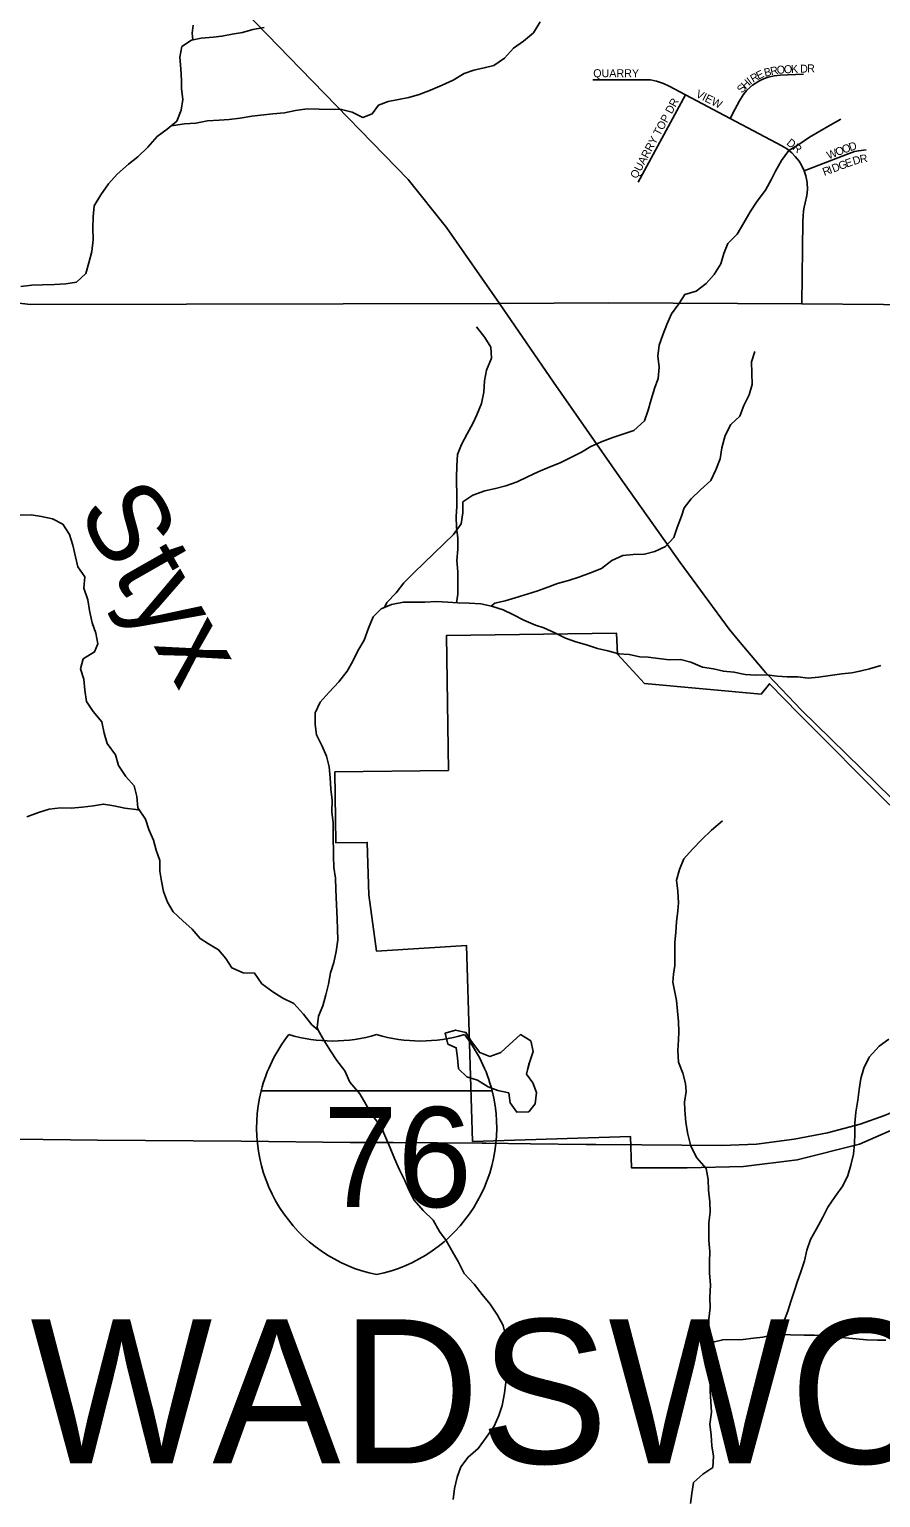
# Model space of a CAD drawing. Extents: x 1985906 to 2277390, y 930619 to 1324581.
# Drawn here: x 2165801 to 2171119, y 1102890 to 1112061 of the extents above; entities that cross this region are included whole.
import ezdxf

# ---------------------------------------------------------------- set-up
doc = ezdxf.new("R2010")
doc.units = 0
for name, color, linetype in [('GM_X_Corporation', 7, 'Continuous'), ('GM_X_Interstate_Location', 7, 'Continuous'), ('GM_X_Interstate_Route', 7, 'Continuous'), ('GM_X_Interstate_Shield', 7, 'Continuous'), ('GM_X_Minor_Lake', 7, 'Continuous'), ('GM_X_Minor_River', 7, 'Continuous'), ('GM_X_Minor_River_Text', 7, 'Continuous'), ('GM_X_State_Route', 7, 'Continuous'), ('GM_X_Township_Road', 7, 'Continuous'), ('GM_X_Township_Subdivision', 7, 'Continuous'), ('GM_X_Township_Subdivision_Text', 7, 'Continuous'), ('GM_X_Township_Text', 7, 'Continuous')]:
    doc.layers.add(name, color=color, linetype=linetype)

msp = doc.modelspace()

# ---------------------------------------------------------------- linework, layer by layer
at = {"layer": 'GM_X_Corporation'}
msp.add_lwpolyline([(2171300.4, 1105236.1), (2170987.2, 1105097.6), (2170598.2, 1104999.5), (2170261.5, 1104957.3), (2169911.1, 1104949.2), (2169562.4, 1104950.4), (2169556.4, 1105145.4), (2168569.5, 1105114.6), (2168531.3, 1106339.4), (2167970.3, 1106302.3), (2167922.1, 1106655.2), (2167911.9, 1106982.2), (2167715.8, 1106979.5), (2167709.7, 1107422.7), (2168419, 1107432.4), (2168407.4, 1108275.7), (2169468.6, 1108290.2), (2169474.8, 1108158.3), (2169643, 1107975.9), (2170372.1, 1107907.9), (2170423.6, 1107973.1), (2170608.8, 1107785.7), (2171176.3, 1107215.7)], dxfattribs=at)
at = {"layer": 'GM_X_Interstate_Route'}
for points in [[(2169340.5, 1105095.5), (2169627.6, 1105092.7), (2170126.8, 1105089.2), (2170343.8, 1105098.7), (2170579, 1105129.1), (2170786.5, 1105168.2), (2170990.8, 1105223.5), (2171143.3, 1105277.6), (2171307.3, 1105346.1), (2171741.4, 1105556.1)], [(2161235, 1105171.6), (2161289.1, 1105171.1), (2161323.8, 1105170.8), (2161961, 1105162.1), (2161969.6, 1105161.9), (2162147.6, 1105159.5), (2162924.5, 1105156), (2163727.5, 1105147.4), (2164561.7, 1105143), (2165425.4, 1105133.5), (2165719.2, 1105129.6), (2166226.6, 1105123.1), (2167123.3, 1105116.1), (2167804.7, 1105109.2), (2168074.7, 1105108.3), (2168630.3, 1105104), (2168655.3, 1105103.6)], [(2168655.3, 1105103.6), (2168931.5, 1105099.6), (2169279.6, 1105096.1), (2169340.5, 1105095.5)]]:
    msp.add_lwpolyline(points, dxfattribs=at)
at = {"layer": 'GM_X_Interstate_Shield'}
for p, q in [((2167249.1, 1105431.2), (2168691.8, 1105431.2)), ((2168691.8, 1105431.2), (2167249.1, 1105431.2)), ((2168691.8, 1105431.2), (2167249.1, 1105431.2))]:
    msp.add_line(p, q, dxfattribs=at)
for centre, start, end in [((2168158, 1105201.3), 141.66896, 165.80665), ((2167696.5, 1106679.4), 253.00908, 286.99093), ((2168244.4, 1106679.4), 253.00908, 286.99093), ((2167783, 1105201.3), 14.19335, 38.33104), ((2168158, 1105201.3), 165.80665, 258.46304), ((2167783, 1105201.3), 281.53696, 14.19335)]:
    msp.add_arc(centre, 937.5, start, end, dxfattribs=at)
at = {"layer": 'GM_X_Minor_Lake'}
for points in [[(2168914, 1105568), (2168924.5, 1105608.5), (2168949.2, 1105677.1), (2168934, 1105742.9), (2168869.2, 1105781.8), (2168798.2, 1105718.3), (2168747, 1105671.3), (2168677.4, 1105645.9), (2168614.9, 1105670.8), (2168563.5, 1105740), (2168528.4, 1105795.4), (2168464.1, 1105810.3), (2168398.3, 1105791), (2168415.6, 1105723.2)], [(2168921.4, 1105596.7), (2168924.5, 1105608.5), (2168949.2, 1105677.1), (2168934, 1105742.9), (2168869.2, 1105781.8), (2168798.2, 1105718.3), (2168747, 1105671.3), (2168677.4, 1105645.9), (2168614.9, 1105670.8), (2168563.5, 1105740), (2168528.4, 1105795.4), (2168464.1, 1105810.3), (2168398.3, 1105791), (2168415.6, 1105723.2)], [(2168415.6, 1105723.2), (2168468.1, 1105700.1), (2168475.3, 1105636.2), (2168482.6, 1105568.2), (2168533.6, 1105519), (2168600.1, 1105498.2), (2168667, 1105455.4), (2168727.5, 1105432.5), (2168795.8, 1105417.8), (2168805, 1105355.8), (2168846.1, 1105298.5), (2168920.2, 1105299.9), (2168961.3, 1105350.7), (2168970, 1105421), (2168946.9, 1105480.7), (2168905.8, 1105536), (2168914, 1105568)], [(2168415.6, 1105723.2), (2168468.1, 1105700.1), (2168475.3, 1105636.2), (2168482.6, 1105568.2), (2168533.6, 1105519), (2168600.1, 1105498.2), (2168667, 1105455.4), (2168727.5, 1105432.5), (2168795.8, 1105417.8), (2168805, 1105355.8), (2168846.1, 1105298.5), (2168920.2, 1105299.9), (2168961.3, 1105350.7), (2168970, 1105421), (2168946.9, 1105480.7), (2168905.8, 1105536), (2168921.4, 1105596.7)]]:
    msp.add_lwpolyline(points, dxfattribs=at)
at = {"layer": 'GM_X_Minor_River'}
for points in [[(2165747.8, 1110455.7), (2165815.7, 1110463), (2165883.8, 1110464.2), (2165957.9, 1110467.6), (2166027.9, 1110470.9), (2166095.8, 1110482.2), (2166152.9, 1110535.4), (2166173.6, 1110601.9), (2166192.3, 1110674.3), (2166199, 1110746.6), (2166197.6, 1110818.7), (2166200.3, 1110890.8), (2166205, 1110959.1), (2166247.8, 1111028), (2166294.6, 1111097), (2166349.5, 1111156.1), (2166420.5, 1111219.5), (2166479.7, 1111264.7), (2166540.6, 1111325.9), (2166599.5, 1111391.1), (2166662.7, 1111436.4), (2166721.9, 1111487.6), (2166748.6, 1111556.2), (2166759.4, 1111622.5), (2166752.1, 1111690.5), (2166751.2, 1111740.5), (2166747.8, 1111814.6), (2166740.4, 1111886.6), (2166753.2, 1111952.9), (2166814.5, 1111994.1), (2166874.4, 1112005.3), (2166948.4, 1112012.7), (2167004.4, 1112017.7), (2167068.2, 1112030.9), (2167132.1, 1112042.1), (2167197.8, 1112059.4), (2167267.7, 1112072.7)], [(2166688.1, 1111458.4), (2166702.3, 1111461.2), (2166770.3, 1111470.4), (2166840.3, 1111475.8), (2166914.1, 1111489.2), (2166986.1, 1111494.5), (2167050.1, 1111497.7), (2167118.1, 1111507), (2167189.9, 1111518.4), (2167321.9, 1111532.8), (2167395.8, 1111540.2), (2167463.7, 1111553.5), (2167537.5, 1111564.9), (2167611.7, 1111562.3), (2167751.9, 1111560.9), (2167818.3, 1111544.1), (2167885, 1111511.3), (2167942.7, 1111532.4), (2167981.7, 1111587.2), (2168043.4, 1111610.4), (2168107.2, 1111623.6), (2168171.1, 1111634.8), (2168236.8, 1111654.1), (2168306.4, 1111681.4), (2168379.9, 1111712.9), (2168449.4, 1111744.2), (2168516.8, 1111785.5), (2168578.5, 1111806.7), (2168642.3, 1111819.9), (2168702.1, 1111835.1), (2168769.3, 1111880.4), (2168826.2, 1111943.6), (2168887.5, 1111986.8), (2168950.6, 1112040.1), (2168991.4, 1112106.9)], [(2166822.9, 1111995.7), (2166817.7, 1112036.3), (2166824.8, 1112086.5)], [(2168018.9, 1108450.1), (2168033.8, 1108480.9), (2168092.7, 1108542.1), (2168139.6, 1108603.1), (2168204.5, 1108668.4), (2168265.5, 1108725.7), (2168328.5, 1108787), (2168391.4, 1108850.2), (2168450.4, 1108905.4), (2168499.2, 1108972.5), (2168508, 1109040.7), (2168508.7, 1109108.9), (2168572, 1109152.1), (2168645.6, 1109177.5), (2168713.4, 1109192.8), (2168777.2, 1109210.1), (2168848.8, 1109235.4), (2168912.3, 1109266.7), (2168979.8, 1109298), (2169047.4, 1109327.3), (2169117, 1109352.6), (2169184.4, 1109385.9), (2169249.9, 1109419.2), (2169309.3, 1109454.4), (2169378.9, 1109485.7), (2169446.5, 1109511), (2169514.1, 1109534.3), (2169577.8, 1109555.6), (2169642.8, 1109614.9), (2169667.6, 1109681.4), (2169686.4, 1109747.9), (2169707.1, 1109818.4), (2169730, 1109881), (2169734.7, 1109951.2), (2169727.4, 1110019.1), (2169736.1, 1110087.4), (2169759, 1110152), (2169783.8, 1110216.5), (2169812.6, 1110283.2), (2169857.5, 1110346.1), (2169896.4, 1110405), (2169966.1, 1110426.3), (2170029.3, 1110473.6), (2170078.3, 1110530.6), (2170121.2, 1110595.5), (2170140, 1110659.9), (2170164.9, 1110722.5), (2170221.8, 1110781.6), (2170264.6, 1110852.6), (2170303.3, 1110921.4), (2170348.2, 1110988.4), (2170398.9, 1111057.4), (2170437.7, 1111124.2), (2170462.8, 1111174.8), (2170499.6, 1111241.6), (2170544.5, 1111304.5), (2170607.9, 1111341.8), (2170675.2, 1111387.1), (2170738.6, 1111424.3), (2170803.9, 1111461.6), (2170869.3, 1111498.9)], [(2168469.5, 1108479.9), (2168477.4, 1108533.3), (2168478.1, 1108603.4), (2168476.8, 1108673.5), (2168471.5, 1108743.5), (2168478.1, 1108813.8), (2168476.8, 1108883.9), (2168469.6, 1108949.9), (2168468.3, 1109018), (2168471.2, 1109080.1), (2168472.2, 1109130.2), (2168469.8, 1109262.4), (2168472.4, 1109334.6), (2168475.1, 1109404.8), (2168500, 1109467.3), (2168536.8, 1109534.1), (2168573.6, 1109602.9), (2168596.7, 1109653.4), (2168625.4, 1109724.1), (2168640.1, 1109794.5), (2168644.8, 1109864.7), (2168657.5, 1109933.1), (2168688.2, 1110007.8), (2168682.9, 1110075.8), (2168645.7, 1110137.2), (2168594.4, 1110202.3)], [(2168687.9, 1108459.3), (2168708.7, 1108477.5), (2168772.6, 1108490.7), (2168836.3, 1108509.9), (2168971.7, 1108552.5), (2169039.3, 1108577.8), (2169101, 1108599), (2169168.7, 1108618.3), (2169234.4, 1108639.6), (2169306, 1108667), (2169375.6, 1108694.3), (2169438.8, 1108743.6), (2169508.3, 1108774.9), (2169572.3, 1108780.1), (2169644.3, 1108783.5), (2169708.1, 1108798.7), (2169775.6, 1108830), (2169826.6, 1108887.1), (2169847.5, 1108949.5), (2169874.2, 1109020.2), (2169891.3, 1109072.6), (2169934.3, 1109127.5), (2169993.3, 1109184.7), (2170058.3, 1109242), (2170089.1, 1109308.7), (2170115.8, 1109379.3), (2170126.6, 1109447.6), (2170147.2, 1109524.1), (2170184, 1109592.9), (2170239.1, 1109644), (2170263.9, 1109710.6), (2170296.7, 1109777.3), (2170315.5, 1109841.8), (2170312.8, 1109984), (2170333.7, 1110048.5)], [(2167604.9, 1105810.3), (2167566.2, 1105843.6), (2167512.9, 1105910.7), (2167453.6, 1105975.7), (2167384.9, 1106010.5), (2167322.1, 1106049.4), (2167253, 1106100.2), (2167207.8, 1106165.5), (2167137.6, 1106168.2), (2167066.9, 1106198.9), (2167027.8, 1106258.3), (2166982.7, 1106311.6), (2166920, 1106348.4), (2166867.3, 1106381.5), (2166818.1, 1106440.7), (2166759.1, 1106491.7), (2166699.9, 1106548.7), (2166664.7, 1106610.1), (2166639.5, 1106675.8), (2166626.3, 1106739.7), (2166617.1, 1106803.6), (2166615.8, 1106869.7), (2166592.6, 1106933.4), (2166577.4, 1106997.2), (2166548.2, 1107062.8), (2166526.9, 1107128.5), (2166479.5, 1107197.7), (2166472.2, 1107269.7), (2166454.9, 1107335.5), (2166403.8, 1107394.6), (2166358.5, 1107461.9), (2166339.2, 1107529.7), (2166287.8, 1107600.9), (2166268.6, 1107664.6), (2166253.2, 1107736.4), (2166199.9, 1107799.6), (2166158.7, 1107862.9), (2166147.4, 1107932.8), (2166142.1, 1108002.8), (2166120.9, 1108066.6), (2166137.7, 1108129), (2166209, 1108172.4), (2166228.1, 1108222.8), (2166216.9, 1108288.7), (2166193.6, 1108354.4), (2166176.2, 1108430.2), (2166166.9, 1108498.2), (2166141.5, 1108569.8), (2166148.2, 1108642.1), (2166103, 1108703.3), (2166089.8, 1108765.2), (2166072.4, 1108839), (2166051.1, 1108904.7), (2166009.9, 1108970.1), (2165945.2, 1109002.9), (2165876.8, 1109017.6), (2165812.5, 1109028.5), (2165744.4, 1109027.2)], [(2167604.9, 1105810.3), (2167598.6, 1105826.2), (2167607.3, 1105896.4), (2167634.2, 1105961.1), (2167652.9, 1106029.5), (2167669.6, 1106098), (2167682.4, 1106168.3), (2167703.2, 1106232.8), (2167717.9, 1106301.2), (2167728.6, 1106373.6), (2167725.4, 1106437.6), (2167724.1, 1106505.7), (2167717.7, 1106637.8), (2167714.7, 1106689.8), (2167713.4, 1106760), (2167704.1, 1106825.9), (2167700.8, 1106896), (2167698.2, 1107036.2), (2167698.9, 1107104.3), (2167691.6, 1107174.3), (2167692.3, 1107246.4), (2167685, 1107314.4), (2167679.7, 1107386.4), (2167674.4, 1107454.4), (2167657.1, 1107520.2), (2167629.9, 1107583.8), (2167594.5, 1107655.3), (2167587.3, 1107719.3), (2167586, 1107791.4), (2167616.8, 1107858.1), (2167673.7, 1107921.2), (2167734.6, 1107984.5), (2167787.4, 1108051.6), (2167822.3, 1108114.3), (2167853.1, 1108179), (2167891.9, 1108245.9), (2167918.6, 1108320.5), (2167949.3, 1108391.2), (2167998.4, 1108442.2), (2168064, 1108467.5), (2168137.9, 1108482.9), (2168201.9, 1108484.1), (2168272, 1108483.4), (2168344.1, 1108486.7), (2168416.2, 1108484.1), (2168478.4, 1108479.2), (2168548.5, 1108476.5), (2168620.7, 1108471.9), (2168689, 1108459.1), (2168761.6, 1108434.4), (2168826.3, 1108403.6), (2168891, 1108370.7), (2168963.6, 1108340), (2169014, 1108322.9), (2169082.7, 1108292.1), (2169149.4, 1108257.3), (2169214, 1108234.5), (2169280.4, 1108215.7), (2169350.9, 1108193), (2169415.3, 1108178.1), (2169483.7, 1108159.4), (2169547.9, 1108156.6), (2169614.2, 1108141.8), (2169666.4, 1108138.8), (2169730.6, 1108131.9), (2169796.8, 1108123.2), (2169868.9, 1108124.5), (2169933.3, 1108107.7), (2170006, 1108077), (2170074.3, 1108066.2), (2170136.6, 1108051.4), (2170202.8, 1108046.6), (2170273.2, 1108031.9), (2170339.3, 1108027.1), (2170407.4, 1108028.4), (2170471.6, 1108021.6), (2170535.8, 1108016.7), (2170601.9, 1108016), (2170666.1, 1108009.2), (2170730.1, 1108014.3), (2170804, 1108025.8), (2170875.9, 1108035.1), (2170937.9, 1108042.3), (2170989.8, 1108051.2), (2171049.6, 1108066.4), (2171119.3, 1108087.7)], [(2166489.6, 1107183.1), (2166465.7, 1107187.4), (2166397.5, 1107196.2), (2166329.1, 1107210.9), (2166264.8, 1107221.8), (2166200.9, 1107210.6), (2166131, 1107203.2), (2166063, 1107196), (2165994.9, 1107198.7), (2165924.9, 1107189.4), (2165857.2, 1107170.1), (2165785.6, 1107142.7)], [(2170049.2, 1104363.2), (2170052, 1104427.4), (2170044.7, 1104495.4), (2170045.8, 1104545.5), (2170046.6, 1104605.6), (2170053.4, 1104673.8), (2170052.2, 1104737.9), (2170042.8, 1104809.9), (2170041.6, 1104878), (2170028.3, 1104945.9), (2169971, 1105012.9), (2169933.5, 1105086.3), (2169914.1, 1105160.1), (2169902.8, 1105234), (2169895.3, 1105310), (2169894.4, 1105360.1), (2169903.2, 1105426.4), (2169900.2, 1105476.4), (2169883, 1105542.2), (2169855.7, 1105609.8), (2169852.3, 1105681.9), (2169857.1, 1105750.1), (2169858.1, 1105800.2), (2169857, 1105864.3), (2169849.8, 1105928.3), (2169844.5, 1105994.3), (2169833.5, 1106046.2), (2169820.3, 1106110.1), (2169825.4, 1106160.2), (2169832.4, 1106214.5), (2169833.2, 1106278.6), (2169833.8, 1106356.8), (2169838.6, 1106420.9), (2169843.3, 1106487.2), (2169852.1, 1106555.4), (2169855.2, 1106605.6), (2169851.8, 1106677.6), (2169844.5, 1106747.6), (2169863.3, 1106814.1), (2169890.1, 1106880.7), (2169943.1, 1106939.8), (2170002, 1107001), (2170063, 1107058.2), (2170130, 1107117.6)], [(2168448.6, 1102878.8), (2168457.4, 1102947.1), (2168474.1, 1103017.5), (2168496.9, 1103082), (2168541.8, 1103143), (2168604.9, 1103196.2), (2168653.7, 1103265.3), (2168704.5, 1103336.3), (2168733.3, 1103403), (2168754.1, 1103465.5), (2168768.7, 1103541.9), (2168777.4, 1103612.2), (2168782.1, 1103684.4), (2168780.7, 1103760.5), (2168773.5, 1103824.5), (2168776, 1103904.7), (2168760.8, 1103964.5), (2168725.6, 1104030), (2168680.2, 1104099.2), (2168629.1, 1104158.4), (2168579.8, 1104223.6), (2168516.4, 1104290.6), (2168479, 1104364), (2168441.8, 1104429.4), (2168404.5, 1104496.8), (2168363.4, 1104552.2), (2168324, 1104623.6), (2168260.8, 1104682.5), (2168205.5, 1104747.6), (2168174.3, 1104809.1), (2168147.1, 1104870.7), (2168113.8, 1104938.2), (2168082.5, 1105007.7), (2168055.2, 1105075.3), (2168028, 1105136.9), (2167998.7, 1105206.5), (2167943.3, 1105279.6), (2167904, 1105347), (2167864.7, 1105412.4), (2167803.2, 1105485.4), (2167771.9, 1105554.9), (2167722.6, 1105620.1), (2167681.4, 1105681.5), (2167640.1, 1105746.8), (2167604.9, 1105810.3)], [(2170496.9, 1103908.5), (2170496.6, 1103916.6), (2170512.9, 1103983.2), (2170539.6, 1104053.8), (2170558.5, 1104114.3), (2170581.2, 1104182.8), (2170598.3, 1104235.2), (2170621.1, 1104299.8), (2170643.9, 1104368.3), (2170658.6, 1104436.7), (2170681.4, 1104503.2), (2170718.3, 1104568), (2170755, 1104636.8), (2170789.8, 1104703.6), (2170834.6, 1104770.6), (2170883.5, 1104837.6), (2170914.3, 1104902.3), (2170933.1, 1104966.8), (2170949.9, 1105035.2), (2170954.6, 1105101.4), (2170957.5, 1105163.6), (2170958.3, 1105229.7), (2170963, 1105297.9), (2170975.6, 1105372.2), (2170984.4, 1105438.5), (2170995.1, 1105508.9), (2171013.9, 1105573.3), (2171046.7, 1105642.1), (2171109.5, 1105709.3), (2171170.8, 1105752.6)], [(2169931.1, 1102854.3), (2169939.9, 1102916.6), (2169950.7, 1102984.9), (2170007.8, 1103036.1), (2170071.1, 1103079.3), (2170075.8, 1103149.6), (2170064.6, 1103213.5), (2170059.3, 1103279.5), (2170052, 1103349.5), (2170062.7, 1103423.8), (2170057.5, 1103487.8), (2170054.2, 1103557.9), (2170051.9, 1103678.1), (2170054.7, 1103744.2), (2170053.3, 1103816.3), (2170048.1, 1103880.3), (2170045.8, 1104004.5), (2170054.5, 1104074.8), (2170051.3, 1104140.9), (2170055.8, 1104219.1), (2170050.5, 1104293.1), (2170049.2, 1104363.2)], [(2170049.5, 1103863.3), (2170080.5, 1103862.9), (2170132.3, 1103875.9), (2170260.5, 1103878.3), (2170324.4, 1103885.5), (2170382.4, 1103892.6), (2170436.2, 1103905.6), (2170506.2, 1103908.9), (2170556.3, 1103907.8), (2170640.5, 1103905.4), (2170706.6, 1103904.6), (2170756.7, 1103901.6), (2170827, 1103892.9), (2170897.1, 1103888.2), (2170965.4, 1103881.4), (2171031.5, 1103876.6), (2171099.7, 1103873.9), (2171151.8, 1103872.9)]]:
    msp.add_lwpolyline(points, dxfattribs=at)
at = {"layer": 'GM_X_State_Route'}
for points in [[(2170242.4, 1108231.6), (2170173.3, 1108313.8), (2169867.2, 1108729.9), (2169487.9, 1109265.9), (2169076.2, 1109858), (2168737.9, 1110348.5), (2168407.6, 1110823.9), (2168167.2, 1111123.6), (2167494.7, 1111814.8), (2166521.6, 1112818.7), (2165729.7, 1113637.3), (2165650.7, 1113722.2), (2165606.3, 1113769.9), (2165436.8, 1113920.9), (2165291.9, 1114007.2), (2164643.9, 1114289.7), (2164576.1, 1114328.1), (2164516, 1114338.4), (2164395.9, 1114349.1), (2163591.1, 1114373.4), (2163265.7, 1114371.3)], [(2170413.5, 1108029.8), (2170401.7, 1108042.1), (2170242.4, 1108231.6)], [(2171200.4, 1107245.4), (2171185.2, 1107261.1), (2170624.8, 1107809.3), (2170413.5, 1108029.8)]]:
    msp.add_lwpolyline(points, dxfattribs=at)
at = {"layer": 'GM_X_Township_Road'}
for points in [[(2165559.8, 1110430.1), (2165621.5, 1110383.4), (2165679.9, 1110362.3), (2165720.6, 1110351.7), (2165807.1, 1110343.3), (2168737.9, 1110348.5)], [(2168737.9, 1110348.5), (2168737.9, 1110348.5), (2169421.2, 1110353.4), (2170625.6, 1110346), (2171135.7, 1110342.8), (2173245.3, 1110339.3), (2175570.1, 1110360.4)]]:
    msp.add_lwpolyline(points, dxfattribs=at)
at = {"layer": 'GM_X_Township_Subdivision'}
for points in [[(2170178.6, 1111504.5), (2170207.8, 1111559.8), (2170237.1, 1111615), (2170259.7, 1111651.3), (2170283.7, 1111680.3), (2170319.2, 1111712.4), (2170358.6, 1111738.1), (2170387.2, 1111751.8), (2170417.2, 1111762.4), (2170455.5, 1111771.1), (2170490.2, 1111774.5), (2170636.3, 1111780.4)], [(2170625.6, 1110346), (2170632.9, 1110862.9), (2170634.4, 1110894.8), (2170637.9, 1110926.4), (2170641.9, 1110950.1), (2170647.9, 1110977.5), (2170658.4, 1111024.1), (2170661.5, 1111061.6), (2170659.4, 1111105), (2170651.3, 1111146.5), (2170641.4, 1111176.7), (2170624.5, 1111212.9), (2170609.2, 1111237.8), (2170585.8, 1111267.7), (2170564, 1111289.8), (2170536.6, 1111312), (2170501.9, 1111333.5), (2170360.3, 1111408.4), (2170178.6, 1111504.5), (2169899.9, 1111652), (2169797.3, 1111706.2), (2169763.4, 1111722.9), (2169718.2, 1111738), (2169681.6, 1111744.6), (2169590, 1111746.5), (2169320.5, 1111745.7)], [(2169604.6, 1111106.5), (2169899.9, 1111652)], [(2170641.4, 1111176.7), (2170879.2, 1111268.8), (2170921.7, 1111285.2), (2170956.3, 1111297.4), (2170980.1, 1111302.9), (2171029.4, 1111307.4)]]:
    msp.add_lwpolyline(points, dxfattribs=at)

# ---------------------------------------------------------------- texts
at = {"layer": 'GM_X_Interstate_Location'}
for s in ['-', '.', ',']:
    msp.add_text(s, height=1, dxfattribs=at).set_placement((2167970.3, 1105032.3))
msp.add_text('76', height=1, rotation=0.00001, dxfattribs=at).set_placement((2167766, 1104825.3))
at = {"layer": 'GM_X_Interstate_Shield'}
msp.add_text('76', height=625, dxfattribs=at).set_placement((2167636.4, 1104704.7))
at = {"layer": 'GM_X_Minor_River_Text'}
msp.add_text('Styx', height=500.21, rotation=299.65502, dxfattribs=at).set_placement((2166095.5, 1109054.2))
at = {"layer": 'GM_X_Township_Subdivision_Text'}
for s, rotation, p in [('QUARRY', 0.00001, (2169323.6, 1111761.9)), ('R', 30.06416, (2170322.1, 1111726.2)), ('E', 26.44288, (2170355.6, 1111745.6)), ('B', 13.3295, (2170396.9, 1111764.4)), ('R', 11.86239, (2170435.1, 1111773.5)), ('O', 5.97811, (2170472.5, 1111781.4)), ('O', 2.1858, (2170515.4, 1111785.9)), ('K', 2.01109, (2170559.3, 1111787.6)), ('D', 1.98924, (2170616.5, 1111789.6)), ('R', 2.02423, (2170660.5, 1111791.1)), ('VIEW', 333.43768, (2169960.3, 1111641.1)), ('S', 49.38981, (2170253.5, 1111658.4)), ('H', 44.18088, (2170275.5, 1111684.3)), ('I', 36.90487, (2170305.8, 1111713.9)), ('QUARRY TOP DR', 61.59401, (2169594.8, 1111123.8)), ('DR', 320.9015, (2170526.6, 1111344.3)), ('W', 21.40806, (2170794.2, 1111247.7)), ('O', 21.40778, (2170847.4, 1111268.6)), ('O', 20.03165, (2170888.1, 1111284.5)), ('D', 17.40488, (2170928.9, 1111299.4)), ('D', 20.31662, (2170824.8, 1111166.5)), ('G', 20.31662, (2170866.1, 1111181.8)), ('E', 19.85236, (2170907.2, 1111197)), ('D', 16.37474, (2170952.1, 1111213)), ('R', 9.63799, (2170992.8, 1111225)), ('R', 20.3088, (2170767, 1111145.1)), ('I', 20.30156, (2170804.2, 1111158.9))]:
    msp.add_text(s, height=50, rotation=rotation, dxfattribs=at).set_placement(p)
at = {"layer": 'GM_X_Township_Text'}
msp.add_text('WADSWORTH', height=900, rotation=0.00001, dxfattribs=at).set_placement((2165807.6, 1103103.5))

doc.saveas('drawing.dxf')
